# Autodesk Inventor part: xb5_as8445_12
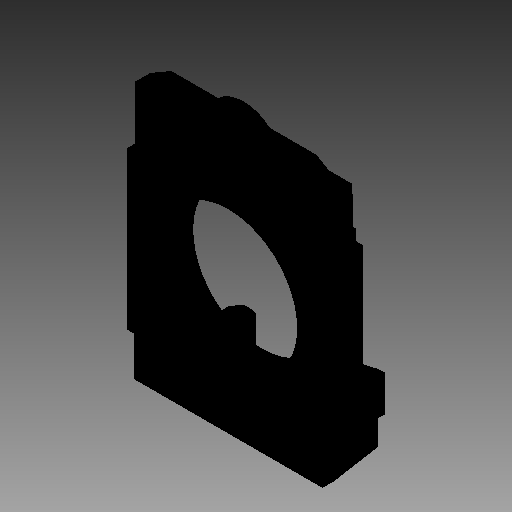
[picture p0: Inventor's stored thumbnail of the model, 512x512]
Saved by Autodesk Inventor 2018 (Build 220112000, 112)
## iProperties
Company: TraceParts S.A.
Created: 2018-04
Part Number: xb5_as8445_12
Checked By: TraceParts S.A.
Material: Generic
Catalog Web Link: www.traceparts.com
Document SubType Name: Modeling
Designer: TraceParts
Density: 1 g/cm^3
Appearance: Default
Author: TraceParts
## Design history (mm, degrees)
feature "xb5_as8445_12.ipt"
body "Solid1"
